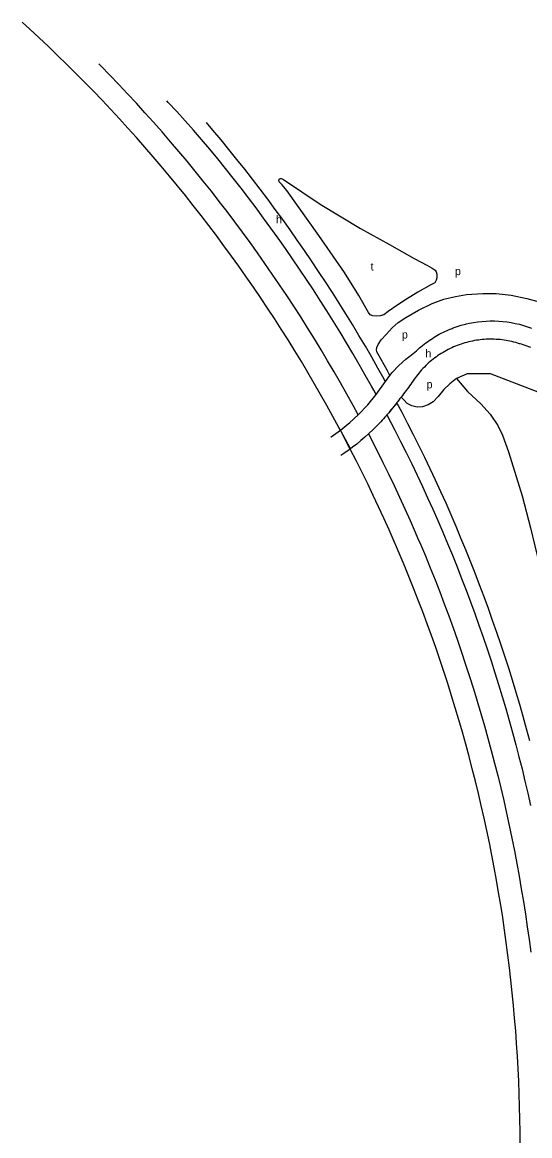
# Model space of a CAD drawing. Extents: x 157569 to 159501, y 382907 to 384670.
# Drawn here: x 157569 to 157822, y 384113 to 384670 of the extents above; entities that cross this region are included whole.
import ezdxf

# ---------------------------------------------------------------- set-up
doc = ezdxf.new("R2010")
doc.units = 0
for name, color, linetype in [('BLT_Basislijn', 7, 'Continuous'), ('BLT_Centroide', 7, 'Continuous'), ('BLT_Vlakafsluiter', 7, 'Continuous')]:
    doc.layers.add(name, color=color, linetype=linetype)

msp = doc.modelspace()

# ---------------------------------------------------------------- linework, layer by layer
at = {"layer": 'BLT_Basislijn'}
for p, q in [((157745.6, 384483.83), (157750.25, 384490.43)), ((157741.45, 384478.75), (157745.6, 384483.83)), ((157736.67, 384473.77), (157741.45, 384478.75)), ((157727.81, 384466.08), (157732.47, 384469.89)), ((157732.47, 384469.89), (157736.67, 384473.77)), ((157723.11, 384462.73), (157727.77, 384466.05)), ((157727.77, 384466.05), (157727.81, 384466.08)), ((157722.96, 384462.63), (157723.11, 384462.73))]:
    msp.add_line(p, q, dxfattribs=at)
for points in [[(157727.77, 384466.05), (157727.05, 384467.39), (157724.03, 384472.95), (157720.97, 384478.48), (157717.85, 384483.99), (157714.7, 384489.48), (157711.49, 384494.94), (157708.24, 384500.37), (157704.95, 384505.77), (157701.61, 384511.15), (157698.22, 384516.5), (157694.8, 384521.81), (157691.32, 384527.11), (157687.81, 384532.37), (157684.25, 384537.6), (157680.64, 384542.8), (157677, 384547.97), (157673.31, 384553.11), (157669.57, 384558.23), (157665.8, 384563.3), (157661.98, 384568.35), (157658.12, 384573.37), (157654.22, 384578.35), (157650.28, 384583.3), (157646.29, 384588.22), (157642.27, 384593.1), (157638.2, 384597.95), (157634.1, 384602.77), (157629.95, 384607.55), (157625.77, 384612.3), (157621.54, 384617.01), (157617.28, 384621.69), (157612.98, 384626.33), (157608.64, 384630.94), (157604.26, 384635.51), (157599.84, 384640.04), (157595.39, 384644.53), (157590.89, 384648.99), (157586.37, 384653.41), (157581.8, 384657.79), (157577.2, 384662.14), (157572.56, 384666.44), (157568.72, 384669.95)], [(157736.67, 384473.77), (157734.12, 384478.48), (157731.01, 384484.1), (157727.85, 384489.69), (157724.64, 384495.26), (157721.39, 384500.8), (157718.09, 384506.31), (157714.74, 384511.8), (157711.35, 384517.25), (157707.92, 384522.68), (157704.44, 384528.08), (157700.91, 384533.45), (157697.34, 384538.8), (157693.73, 384544.11), (157690.07, 384549.39), (157686.37, 384554.64), (157682.62, 384559.86), (157678.83, 384565.05), (157675, 384570.2), (157671.12, 384575.33), (157667.21, 384580.42), (157663.25, 384585.48), (157659.24, 384590.5), (157655.2, 384595.49), (157651.11, 384600.45), (157646.99, 384605.38), (157642.82, 384610.27), (157638.61, 384615.12), (157634.36, 384619.94), (157630.08, 384624.72), (157625.75, 384629.47), (157621.38, 384634.18), (157616.97, 384638.86), (157612.53, 384643.5), (157608.04, 384648.1), (157607.02, 384649.13)], [(157745.6, 384483.83), (157745.57, 384483.88), (157744.4, 384486.02), (157743.28, 384488.05), (157740.23, 384493.5), (157737.13, 384498.92), (157734, 384504.32), (157730.81, 384509.7), (157727.59, 384515.05), (157724.32, 384520.37), (157721.01, 384525.67), (157717.66, 384530.94), (157714.27, 384536.19), (157710.83, 384541.4), (157707.36, 384546.59), (157703.84, 384551.75), (157700.28, 384556.89), (157696.68, 384561.99), (157693.04, 384567.07), (157689.36, 384572.12), (157685.64, 384577.13), (157681.88, 384582.12), (157678.08, 384587.08), (157674.24, 384592.01), (157670.36, 384596.9), (157666.43, 384601.76), (157662.44, 384606.57), (157658.4, 384611.32), (157654.29, 384616.03), (157650.13, 384620.68), (157645.94, 384625.31), (157641.72, 384629.91), (157641.05, 384630.63)], [(157750.25, 384490.43), (157750.22, 384490.48), (157749.62, 384491.57), (157746.54, 384497.07), (157743.42, 384502.54), (157740.25, 384507.99), (157737.04, 384513.42), (157733.78, 384518.82), (157730.49, 384524.19), (157727.15, 384529.54), (157723.76, 384534.86), (157720.34, 384540.15), (157716.87, 384545.41), (157713.36, 384550.65), (157709.81, 384555.86), (157706.22, 384561.04), (157702.59, 384566.19), (157698.92, 384571.32), (157695.2, 384576.41), (157691.45, 384581.48), (157687.65, 384586.51), (157683.82, 384591.51), (157679.94, 384596.48), (157676.03, 384601.43), (157672.07, 384606.34), (157668.08, 384611.22), (157664.05, 384616.06), (157660.81, 384619.89)], [(157752.43, 384493.37), (157751.19, 384496.13), (157746.57, 384504.08), (157746.05, 384505.15), (157745.84, 384506.22), (157746.02, 384507.48), (157746.63, 384508.91), (157748.16, 384511.21), (157750.61, 384513.9), (157753.66, 384517.23), (157756.65, 384519.86), (157760.4, 384522.43), (157766.87, 384526.06), (157773.62, 384529.46), (157779.45, 384531.59), (157785.34, 384532.93), (157790.85, 384533.89), (157798.99, 384534.43), (157805.62, 384534.32), (157813.22, 384533.52), (157820.98, 384531.86), (157827.21, 384530.17)], [(157765.06, 384505.1), (157765.79, 384505.8), (157766.53, 384506.48), (157767.29, 384507.15), (157768.06, 384507.8), (157768.84, 384508.44), (157769.63, 384509.06), (157770.43, 384509.67), (157771.24, 384510.27), (157772.07, 384510.85), (157772.9, 384511.42), (157773.75, 384511.97), (157774.6, 384512.5), (157775.46, 384513.02), (157776.34, 384513.52), (157777.22, 384514.01), (157778.11, 384514.48), (157779.01, 384514.94), (157779.92, 384515.38), (157780.83, 384515.8), (157781.76, 384516.21), (157782.69, 384516.59), (157783.62, 384516.97), (157784.21, 384517.19), (157786.19, 384517.89), (157788.2, 384518.51), (157790.23, 384519.05), (157790.86, 384519.21), (157792.28, 384519.52), (157794.34, 384519.91), (157796.42, 384520.22), (157798.5, 384520.45), (157800.6, 384520.61), (157802.7, 384520.68), (157804.8, 384520.68), (157806.9, 384520.59), (157808.99, 384520.43), (157811.08, 384520.18), (157813.15, 384519.86), (157815.21, 384519.46), (157817.26, 384518.98), (157819.28, 384518.42), (157821.29, 384517.79), (157823.26, 384517.08)], [(157823, 384507.4), (157822.05, 384507.73), (157821.11, 384508.05), (157820.16, 384508.37), (157819.21, 384508.69), (157818.27, 384509), (157817.66, 384509.2), (157817.32, 384509.31), (157816.37, 384509.61), (157815.42, 384509.88), (157814.46, 384510.13), (157813.49, 384510.37), (157812.53, 384510.58), (157811.55, 384510.77), (157810.58, 384510.94), (157809.59, 384511.09), (157808.61, 384511.22), (157807.63, 384511.33), (157806.64, 384511.42), (157805.65, 384511.48), (157804.66, 384511.53), (157803.66, 384511.55), (157802.67, 384511.56), (157801.68, 384511.54), (157800.69, 384511.5), (157799.7, 384511.44), (157798.71, 384511.36), (157797.72, 384511.26), (157796.74, 384511.13), (157795.76, 384510.99), (157794.78, 384510.83), (157793.8, 384510.64), (157792.83, 384510.43), (157791.87, 384510.21), (157790.91, 384509.96), (157789.95, 384509.69), (157789, 384509.41), (157788.06, 384509.1), (157787.12, 384508.77), (157786.19, 384508.42), (157785.27, 384508.06), (157784.36, 384507.67), (157783.45, 384507.26), (157782.56, 384506.84), (157781.67, 384506.39), (157780.79, 384505.93), (157779.93, 384505.45), (157779.07, 384504.95), (157778.22, 384504.43), (157777.39, 384503.9), (157776.56, 384503.35), (157775.75, 384502.77), (157774.95, 384502.19), (157774.17, 384501.58), (157773.39, 384500.96), (157772.63, 384500.32), (157771.89, 384499.67), (157771.15, 384499), (157770.44, 384498.32), (157769.73, 384497.62), (157769.04, 384496.9), (157768.37, 384496.17), (157767.71, 384495.43), (157767.07, 384494.68), (157766.45, 384493.9), (157765.84, 384493.12), (157765.25, 384492.33), (157764.72, 384491.59), (157764.67, 384491.52), (157764.1, 384490.7), (157763.52, 384489.88), (157762.94, 384489.06), (157762.35, 384488.25), (157761.76, 384487.44), (157761.17, 384486.63), (157760.58, 384485.83), (157759.98, 384485.02), (157759.38, 384484.22), (157758.77, 384483.42), (157758.16, 384482.63)], [(157752.43, 384493.37), (157753.63, 384494.98), (157756.9, 384498.44), (157760.5, 384501.55), (157762.54, 384503.12), (157765.06, 384505.1)], [(157750.25, 384490.43), (157752.43, 384493.37)], [(157785.74, 384491.86), (157782.42, 384489.29), (157779.49, 384486.33), (157776.65, 384482.96), (157774.09, 384480.28), (157771.62, 384478.68), (157768.79, 384477.82), (157766.22, 384477.66), (157763.44, 384478.25), (157761.19, 384479.43), (157759.42, 384481.25), (157758.16, 384482.63)], [(157802.79, 384494.17), (157791.2, 384494.22), (157785.74, 384491.86)], [(157785.74, 384491.86), (157791.37, 384485.49), (157798.02, 384479.29), (157802.69, 384474.1), (157806.4, 384468.47), (157808.82, 384463.57), (157811.76, 384455.2), (157818.57, 384433.33), (157822.82, 384417.31), (157827.2, 384399.26), (157830.67, 384383.83), (157833.54, 384367.87), (157836.35, 384353.29), (157840.01, 384327.2), (157843.02, 384303.79), (157845.24, 384278.94), (157848.12, 384253.31), (157853.68, 384220.02), (157857.08, 384190.66), (157860.08, 384150.97), (157861.78, 384102.06), (157861.78, 384049.75), (157865.23, 384042.81)], [(158016.56, 384409.49), (157993.85, 384419.91), (157910.36, 384452.84), (157802.79, 384494.17)], [(157756, 384479.84), (157755.7, 384479.47), (157755.08, 384478.68), (157754.45, 384477.9), (157753.82, 384477.12), (157753.19, 384476.35), (157752.56, 384475.57), (157751.92, 384474.8), (157751.5, 384474.31), (157751.27, 384474.03), (157751.04, 384473.75)], [(157758.16, 384482.63), (157757.55, 384481.83), (157756.94, 384481.04), (157756.32, 384480.25), (157756, 384479.84)], [(157756.02, 384479.79), (157756, 384479.84)], [(157822.46, 384310.75), (157820.82, 384316.84), (157819.13, 384322.91), (157817.4, 384328.97), (157815.61, 384335.02), (157813.77, 384341.05), (157811.89, 384347.07), (157809.96, 384353.07), (157807.98, 384359.05), (157805.96, 384365.02), (157803.88, 384370.98), (157801.76, 384376.91), (157799.59, 384382.83), (157797.38, 384388.74), (157795.12, 384394.62), (157792.81, 384400.49), (157790.45, 384406.33), (157788.05, 384412.16), (157785.6, 384417.97), (157783.11, 384423.76), (157780.56, 384429.53), (157777.98, 384435.28), (157775.35, 384441.01), (157772.67, 384446.71), (157769.94, 384452.4), (157767.17, 384458.06), (157764.36, 384463.7), (157761.5, 384469.32), (157758.6, 384474.92), (157756.02, 384479.79)], [(157751.04, 384473.75), (157750.62, 384473.27), (157749.96, 384472.51), (157749.3, 384471.76), (157748.62, 384471.02), (157747.94, 384470.28), (157747.25, 384469.55), (157746.55, 384468.83), (157745.84, 384468.12), (157743.96, 384466.23), (157742.03, 384464.39), (157741.79, 384464.17)], [(157751.04, 384473.75), (157751.06, 384473.71)], [(157751.06, 384473.71), (157755.05, 384466.01), (157757.89, 384460.44), (157760.67, 384454.85), (157763.42, 384449.24), (157766.12, 384443.61), (157768.77, 384437.95), (157771.38, 384432.28), (157773.94, 384426.58), (157776.46, 384420.87), (157778.93, 384415.13), (157781.36, 384409.37), (157783.74, 384403.6), (157786.07, 384397.8), (157788.36, 384391.99), (157790.6, 384386.16), (157792.8, 384380.31), (157794.94, 384374.45), (157797.05, 384368.57), (157799.1, 384362.67), (157801.11, 384356.75), (157803.07, 384350.82), (157804.98, 384344.87), (157806.85, 384338.91), (157808.66, 384332.94), (157810.43, 384326.95), (157812.16, 384320.94), (157813.83, 384314.92), (157815.46, 384308.89), (157817.04, 384302.85), (157818.57, 384296.79), (157820.05, 384290.73), (157821.48, 384284.65), (157822.87, 384278.55)], [(157741.79, 384464.17), (157740.05, 384462.59), (157738.03, 384460.85), (157735.97, 384459.16), (157733.86, 384457.51), (157732.75, 384456.69)], [(157741.79, 384464.17), (157746.1, 384455.74), (157748.97, 384450), (157751.8, 384444.23), (157754.58, 384438.44), (157757.31, 384432.62), (157760, 384426.79), (157762.63, 384420.93), (157765.22, 384415.05), (157766.38, 384412.35), (157767.75, 384409.14), (157770.24, 384403.22), (157772.68, 384397.28), (157775.07, 384391.31), (157777.41, 384385.33), (157779.69, 384379.32), (157781.93, 384373.3), (157784.12, 384367.26), (157786.26, 384361.2), (157788.34, 384355.13), (157790.38, 384349.03), (157792.37, 384342.92), (157794.3, 384336.8), (157796.18, 384330.65), (157798.02, 384324.5), (157799.8, 384318.32), (157801.53, 384312.14), (157803.2, 384305.93), (157804.83, 384299.72), (157806.4, 384293.49), (157807.93, 384287.25), (157809.4, 384280.99), (157810.81, 384274.73), (157812.18, 384268.45), (157813.49, 384262.16), (157814.75, 384255.86), (157815.96, 384249.55), (157817.12, 384243.23), (157818.22, 384236.9), (157819.27, 384230.56), (157820.27, 384224.22), (157821.21, 384217.86), (157822.1, 384211.5), (157822.94, 384205.13)], [(157732.71, 384456.66), (157731.72, 384455.93), (157729.53, 384454.39), (157727.99, 384453.37)], [(157732.75, 384456.69), (157732.71, 384456.66)], [(157817.62, 384109), (157817.58, 384115.33), (157817.49, 384121.66), (157817.35, 384127.99), (157817.15, 384134.31), (157816.91, 384140.64), (157816.61, 384146.96), (157816.25, 384153.28), (157815.85, 384159.59), (157815.39, 384165.9), (157814.88, 384172.21), (157814.31, 384178.52), (157813.7, 384184.82), (157813.03, 384191.11), (157812.31, 384197.4), (157811.53, 384203.68), (157810.71, 384209.95), (157809.83, 384216.22), (157808.9, 384222.48), (157807.92, 384228.73), (157806.88, 384234.98), (157805.8, 384241.21), (157804.66, 384247.44), (157803.47, 384253.65), (157802.23, 384259.86), (157800.93, 384266.05), (157799.59, 384272.24), (157798.19, 384278.41), (157796.74, 384284.57), (157795.24, 384290.72), (157793.69, 384296.86), (157792.09, 384302.98), (157790.44, 384309.09), (157788.73, 384315.18), (157786.98, 384321.26), (157785.18, 384327.33), (157783.32, 384333.38), (157781.41, 384339.42), (157779.46, 384345.43), (157777.45, 384351.44), (157775.4, 384357.42), (157773.29, 384363.39), (157771.14, 384369.34), (157768.93, 384375.27), (157766.68, 384381.19), (157764.37, 384387.08), (157762.02, 384392.96), (157759.62, 384398.81), (157757.17, 384404.65), (157755.82, 384407.81), (157754.67, 384410.46), (157752.12, 384416.26), (157749.53, 384422.03), (157746.89, 384427.78), (157744.19, 384433.51), (157741.46, 384439.21), (157738.67, 384444.89), (157735.84, 384450.55), (157732.71, 384456.66)]]:
    msp.add_lwpolyline(points, dxfattribs=at)
msp.add_lwpolyline([(157699.27, 384591.34), (157717.73, 384579.02), (157737.85, 384566.87), (157752.31, 384558.94), (157764.67, 384551.82), (157771.25, 384548.44), (157773.69, 384547.1), (157775.1, 384546.09), (157775.68, 384545.2), (157775.96, 384543.98), (157775.99, 384542.3), (157775.65, 384541.01), (157774.98, 384539.7), (157773.05, 384538.69), (157766.4, 384534.99), (157760.89, 384531.62), (157756.5, 384528.73), (157751.63, 384525.41), (157749.44, 384523.75), (157747.69, 384523.15), (157745.96, 384523.01), (157743.94, 384523.25), (157742.71, 384523.78), (157741.75, 384524.84), (157736.97, 384533.39), (157729.74, 384544.9), (157716.95, 384563.37), (157701.01, 384585.87), (157698.63, 384588.68), (157697.1, 384590.21), (157696.92, 384590.65), (157696.95, 384591.11), (157697.2, 384591.54), (157697.64, 384591.8), (157698.14, 384591.87), (157698.7, 384591.66)], close=True, dxfattribs=at)
at = {"layer": 'BLT_Vlakafsluiter'}
for p, q in [((157732.71, 384456.66), (157727.77, 384466.05)), ((157732.75, 384456.69), (157727.81, 384466.08))]:
    msp.add_line(p, q, dxfattribs=at)
msp.add_lwpolyline([(157756.02, 384479.79), (157755.74, 384479.44), (157755.12, 384478.65), (157754.49, 384477.87), (157753.86, 384477.09), (157753.23, 384476.31), (157752.59, 384475.54), (157751.95, 384474.77), (157751.54, 384474.27), (157751.31, 384474), (157751.06, 384473.71)], dxfattribs=at)

# ---------------------------------------------------------------- texts
at = {"layer": 'BLT_Centroide'}
for s, p in [('h', (157695.53, 384569.38)), ('t', (157742.88, 384545.88)), ('p', (157785.04, 384543.56)), ('p', (157758.49, 384511.89)), ('h', (157770.23, 384502.45)), ('p', (157770.84, 384487.01))]:
    msp.add_text(s, height=4, dxfattribs=at).set_placement(p)

doc.saveas('drawing.dxf')
